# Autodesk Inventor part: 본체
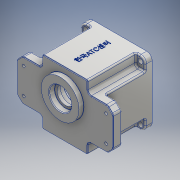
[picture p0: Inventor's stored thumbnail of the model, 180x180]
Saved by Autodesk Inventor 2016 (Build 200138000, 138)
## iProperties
Created: 2017-01
Part Number: 본체
Material: 알루미늄 6061
Document SubType Name: Modeling
Designer: Owner
Density: 2.7 g/cm^3
Appearance: 알루미늄 - 평지
Mass: 874.022 g
Surface Area: 769.042 cm^2
Volume: 323.712 cm^3
Author: Owner
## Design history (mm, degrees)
sketch "스케치1"
  geometry: L1 (47, 47)-(-47, 47); L2 (-47, 47)-(-47, -47); L3 (-47, -47)-(47, -47); L4 (47, -47)-(47, 47); L5 (47, 47)-(-47, -47); L6 (-47, 47)-(47, -47); 1 further point
  constraints: 12 end point, 2 midpoint, 2 parallel, 1 horizontal, 1 perpendicular
  dimensions: "d0" = 94 distance of L2.end L3.end; "d1" = 94 distance of L1.end L2.end
extrude "돌출1" new body sketch "스케치1" distance "d2" = 80; taper "d3" = 0 deg
sketch "스케치2"
  geometry: L1 (0, 0)-(85.477, 0); L2 (9, 0)-(9, 40); L3 (9, 40)-(71, 40); L4 (71, 40)-(71, 43); L5 (71, 43)-(80, 43); L6 (80, 43)-(80, 0); L7 (80, -47)-(80, 47) reference; L8 (0, -47)-(0, 47) reference; L9 (9, 0)-(80, 0)
  constraints: 14 end point, 3 perpendicular, 2 vertical, 1 collinear, 1 horizontal, 1 midpoint, 1 point on line
  dimensions: "d4" = 86 diameter of L5 L1; "d5" = 80 diameter of L3 L1; "d6" = 9 distance of L4.end L5.end; "d7" = 9 distance between parallel lines of L8 L2
revolve "회전1" sketch "스케치2" stored, may be unused: angle "d8" = 90 deg
sketch "스케치3"
  geometry: C1 r 21 at (0, -11); C2 r 15 at (0, 20); 1 further point
  constraints: 2 centre point, 2 vertical alignment
  dimensions: "d9" = 11 distance of point (0, 0) C1.centre; "d10" = 42 diameter of C1; "d13" = 20 distance of C2.centre point (0, 0); "d14" = 30 diameter of C2
extrude "돌출2" join sketch "스케치3" distance "d11" = 7; taper "d12" = 0 deg
hole "구멍1" diameter "d17" = 25; stored, may be unused: countersink angle "d21" = 90 deg, drill point angle "d23" = 118 deg; dims "d15" = 10, "d16" = 10, "d18" = 6, "d19" = 35, "d20" = 10, "d22" = 8
hole "구멍2" diameter "d26" = 19; stored, may be unused: countersink angle "d30" = 90 deg, drill point angle "d32" = 0 deg; dims "d27" = 6, "d28" = 22, "d29" = 7, "d31" = 8, "d33" = 10, "d34" = 10
sketch "스케치5"
  geometry: L1 (-47, 47)-(47, 47) reference; L2 (47, 47)-(47, -47) reference; L3 (47, -47)-(-47, -47) reference; L4 (-47, -47)-(-47, 47) reference; L5 (-33, 47)-(33, 47); L6 (33, 47)-(33, -47); L7 (33, -47)-(-33, -47); L8 (-33, -47)-(-33, 47); L9 (-33, 47)-(33, -47); L10 (33, 47)-(-33, -47); L11 (47, 47)-(47, -47) reference; L12 (-47, 30)-(47, 30); L13 (47, 30)-(47, -30); L14 (47, -30)-(-47, -30); L15 (-47, -30)-(-47, 30); L16 (-47, 30)-(47, -30); L17 (47, 30)-(-47, -30); 1 further point
  constraints: 24 end point, 4 midpoint, 4 parallel, 2 horizontal, 2 perpendicular, 1 horizontal alignment, 1 point on line
  dimensions: "d37" = 66 distance of L5.start L5.end; "d38" = 60 distance of L14.end L12.start
extrude "돌출3" cut sketch "스케치5" distance "d39" = 70; taper "d40" = 0 deg
sketch "스케치6"
  geometry: L1 (70, 30)-(70, -30); L2 (-70, -30)-(-70, 30); L3 (-70, 30)-(70, -30); L4 (70, 30)-(-70, -30); L5 (-47, -30)-(-47, 30) reference; L6 (47, 30)-(47, -30) reference; L7 (-47, 30)-(-47, -30); L8 (-70, 30)-(-47, 30); L9 (47, 30)-(70, 30); L10 (70, -30)-(47, -30); L11 (-47, -30)-(-70, -30); 1 further point
  constraints: 20 end point, 6 equal length, 2 horizontal, 2 midpoint, 2 perpendicular, 1 horizontal alignment
  dimensions: "d41" = 140 distance of L2.end L1.start
extrude "돌출4" join sketch "스케치6" distance "d42" = 13; taper "d43" = 0 deg
sketch "스케치7"
  geometry: C1 r 12.5 at (0, 11) reference; C2 r 27.5 at (0, 11); 1 further point
  constraints: 1 centre point, 1 coincident
  dimensions: "d44" = 55 diameter of C2
extrude "돌출5" join sketch "스케치7" distance "d45" = 7; taper "d46" = 0 deg
hole "구멍3" diameter "d49" = 32; stored, may be unused: countersink angle "d53" = 90 deg, drill point angle "d55" = 0 deg; dims "d50" = 6, "d51" = 22, "d52" = 7, "d54" = 8, "d56" = 10, "d57" = 10
sketch "스케치8" dims "d58" = 72
  geometry: C1 r 40 at (0, 0) reference; A1 r 4 centre (-36, 0) between (-35.852, -3.997) and (-35.852, 3.997); A2 r 40 centre (0, 0) between (-39.148, -8.214) and (-39.148, 8.214) reference; A3 r 3.5 centre (-35.722, -7.495) between (-35.852, -3.997) and (-39.148, -8.214); A4 r 3.5 centre (-35.722, 7.495) between (-39.148, 8.214) and (-35.852, 3.997); 2 further points
  constraints: 8 point on circle, 4 tangent, 3 centre point, 2 horizontal alignment, 1 coincident, 2 other
  dimensions: "d59" = 8 diameter of A1; "d60" = 7 diameter of A3; "d61" = 7 diameter of A4
extrude "돌출6" join sketch "스케치8" stored distance "d62" = 7; taper "d63" = 0 deg
hole "구멍4" diameter "d66" = 3.242; stored, may be unused: countersink angle "d70" = 90 deg, drill point angle "d72" = 118 deg; dims "d64" = 10, "d65" = 10, "d67" = 7, "d68" = 22, "d69" = 7, "d71" = 9
fillet "모깎기1" dims "d73" = 8
sketch "스케치9"
  geometry: 2 further points
  dimensions: "d74" = 40 horizontal distance of point (-40, -40) point (0, 0); "d75" = 40 horizontal distance of point (0, 0) point (-40, -40)
hole "구멍5" sketch "스케치9" at (-40, -40) diameter "d76" = 7; stored, may be unused: countersink angle "d80" = 90 deg, drill point angle "d82" = 118 deg; dims "d77" = 7, "d78" = 22, "d79" = 7, "d81" = 7
chamfer "모따기1" distance "d86" = 8; stored, may be unused: second distance "d87" = 2, angle "d88" = 45 deg
sketch "스케치11"
  geometry: 2 further points
  dimensions: "d92" = 19 vertical distance of point (0, 0) point (-60, -19); "d93" = 60 horizontal distance of point (0, 0) point (-60, -19)
hole "구멍6" sketch "스케치11" at (-60, -19) diameter "d94" = 4; stored, may be unused: countersink angle "d98" = 90 deg, drill point angle "d100" = 118 deg; dims "d95" = 7, "d96" = 10, "d97" = 4, "d99" = 7
fillet "모깎기3" dims "d102" = 2
fillet "모깎기6" dims "d105" = 5
fillet "모깎기7" dims "d106" = 2
fillet "모깎기8" dims "d107" = 5
fillet "모깎기9" dims "d108" = 2
fillet "모깎기10" dims "d109" = 2
fillet "모깎기11" dims "d110" = 0.3
chamfer "모따기2" distance "d111" = 1; stored, may be unused: second distance "d112" = 2, angle "d113" = 45 deg
sketch "스케치12"
  geometry: L1 (33, -45)-(33, -35) reference; L2 (38, -30)-(59.929, -30) reference; L3 (68.536, -23.464)-(63.464, -28.536) reference; L4 (70, -19.929)-(70, 19.929) reference; L5 (63.464, 28.536)-(68.536, 23.464) reference; L6 (59.929, 30)-(38, 30) reference; L7 (33, 35)-(33, 45) reference; L8 (-31, 47)-(31, 47) reference; L9 (-33, 45)-(-33, 35) reference; L10 (-38, 30)-(-59.929, 30) reference; L11 (-68.536, 23.464)-(-63.464, 28.536) reference; L12 (-70, 19.929)-(-70, -19.929) reference; L13 (-63.464, -28.536)-(-68.536, -23.464) reference; L14 (-59.929, -30)-(-38, -30) reference; L15 (-33, -35)-(-33, -45) reference; L16 (31, -47)-(-31, -47) reference; L17 (-32, -45)-(-32, -35); L18 (-38, -29)-(-59.929, -29); L19 (-62.757, -27.828)-(-67.828, -22.757); L20 (-69, -19.929)-(-69, 19.929); L21 (-67.828, 22.757)-(-62.757, 27.828); L22 (-59.929, 29)-(-38, 29); L23 (-32, 35)-(-32, 45); L24 (-31, 46)-(31, 46); L25 (32, 45)-(32, 35); L26 (38, 29)-(59.929, 29); L27 (62.757, 27.828)-(67.828, 22.757); L28 (69, 19.929)-(69, -19.929); L29 (67.828, -22.757)-(62.757, -27.828); L30 (59.929, -29)-(38, -29); L31 (32, -35)-(32, -45); L32 (31, -46)-(-31, -46); C1 r 2 at (60, -19) reference; C2 r 2 at (60, 19) reference; C3 r 2 at (-60, -19) reference; C4 r 2 at (-60, 19) reference; C5 r 27.8 at (0, 11) reference; A1 r 2 centre (31, -45) between (31, -47) and (33, -45) reference; A2 r 5 centre (38, -35) between (38, -30) and (33, -35) reference; A3 r 5 centre (59.929, -25) between (59.929, -30) and (63.464, -28.536) reference; A4 r 5 centre (65, -19.929) between (68.536, -23.464) and (70, -19.929) reference; A5 r 5 centre (65, 19.929) between (70, 19.929) and (68.536, 23.464) reference; A6 r 5 centre (59.929, 25) between (63.464, 28.536) and (59.929, 30) reference; A7 r 5 centre (38, 35) between (33, 35) and (38, 30) reference; A8 r 2 centre (31, 45) between (33, 45) and (31, 47) reference; A9 r 2 centre (-31, 45) between (-31, 47) and (-33, 45) reference; A10 r 5 centre (-38, 35) between (-38, 30) and (-33, 35) reference; A11 r 5 centre (-59.929, 25) between (-59.929, 30) and (-63.464, 28.536) reference; A12 r 5 centre (-65, 19.929) between (-68.536, 23.464) and (-70, 19.929) reference; A13 r 5 centre (-65, -19.929) between (-70, -19.929) and (-68.536, -23.464) reference; A14 r 5 centre (-59.929, -25) between (-63.464, -28.536) and (-59.929, -30) reference; A15 r 5 centre (-38, -35) between (-33, -35) and (-38, -30) reference; A16 r 2 centre (-31, -45) between (-33, -45) and (-31, -47) reference; A17 r 1 centre (-31, -45) between (-32, -45) and (-31, -46); A18 r 6 centre (-38, -35) between (-32, -35) and (-38, -29); A19 r 4 centre (-59.929, -25) between (-62.757, -27.828) and (-59.929, -29); A20 r 4 centre (-65, -19.929) between (-69, -19.929) and (-67.828, -22.757); A21 r 4 centre (-65, 19.929) between (-67.828, 22.757) and (-69, 19.929); A22 r 4 centre (-59.929, 25) between (-59.929, 29) and (-62.757, 27.828); A23 r 6 centre (-38, 35) between (-38, 29) and (-32, 35); A24 r 1 centre (-31, 45) between (-31, 46) and (-32, 45); A25 r 1 centre (31, 45) between (32, 45) and (31, 46); A26 r 6 centre (38, 35) between (32, 35) and (38, 29); A27 r 4 centre (59.929, 25) between (62.757, 27.828) and (59.929, 29); A28 r 4 centre (65, 19.929) between (69, 19.929) and (67.828, 22.757); A29 r 4 centre (65, -19.929) between (67.828, -22.757) and (69, -19.929); A30 r 4 centre (59.929, -25) between (59.929, -29) and (62.757, -27.828); A31 r 6 centre (38, -35) between (38, -29) and (32, -35); A32 r 1 centre (31, -45) between (31, -46) and (32, -45); 1 further point
  constraints: 32 end point, 32 point on circle, 16 centre point, 31 other
  dimensions: "d114" = 1 distance between parallel lines of L16 L32
extrude "돌출7" cut sketch "스케치12" distance "d115" = 1; taper "d116" = 0 deg
sketch "스케치13"
  geometry: L1 (0, 0)-(78, 0) reference; 2 further points
  constraints: 1 vertical alignment, 1 other
  dimensions: "d117" = 40 distance from line of L1 point (39, -40)
feature "엠보싱1" sketch "스케치13" dims "d118" = 0.5, "d119" = 0
fillet "모깎기12" dims "d120" = 2
fillet "모깎기13" dims "d121" = 3
node "솔리드1"
mirror "대칭1"
pattern_circular "원형 패턴1" dims angle "d84" = 360 deg
mirror "대칭2"
mirror "대칭3"
node "투영된 루프1"
node "투영된 루프2"
